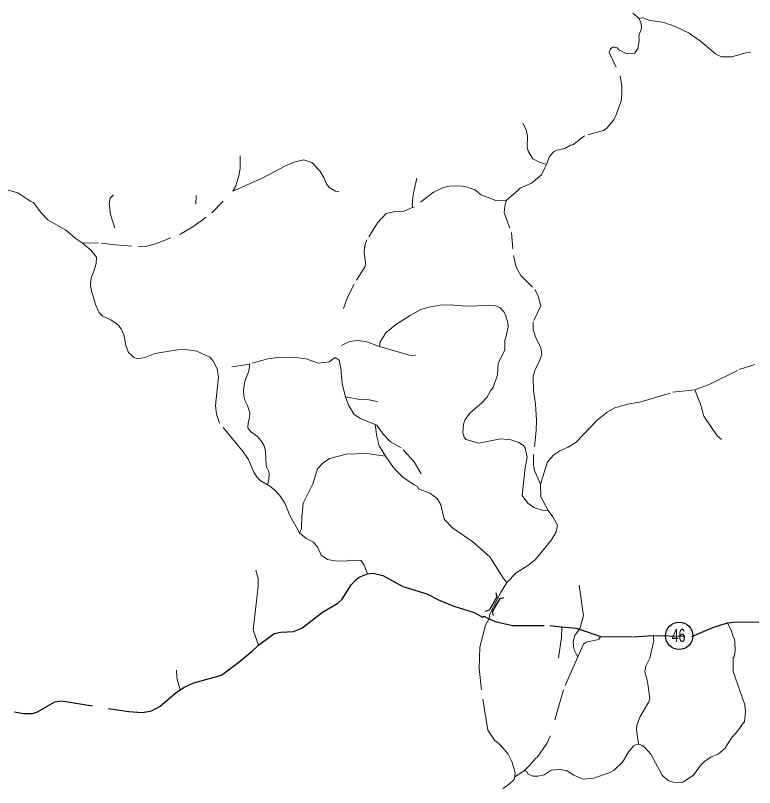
# Model space of a CAD drawing. Extents: x 423 to 448.8, y 7456.3 to 7484.
# Drawn here: x 428.721 to 433.228, y 7474.65 to 7479.36 of the extents above; entities that cross this region are included whole.
import ezdxf
from ezdxf.enums import TextEntityAlignment as Align

# ---------------------------------------------------------------- set-up
doc = ezdxf.new("R2010")
doc.units = 0
doc.header["$LTSCALE"] = 0.032
doc.linetypes.add('LONG_DASHED', pattern=[7.5, 6, -1.5])
doc.linetypes.add('MEDIUM_DASHED', pattern=[4.5, 3, -1.5])
for name, color, linetype, lineweight in [('10', 7, 'Continuous', 25), ('13', 7, 'Continuous', 25), ('4', 7, 'LONG_DASHED', 25), ('5', 7, 'LONG_DASHED', 13), ('6', 7, 'MEDIUM_DASHED', 13), ('7', 7, 'Continuous', 13)]:
    doc.layers.add(name, color=color, linetype=linetype, lineweight=lineweight)
doc.layers.add('61', color=7, linetype='Continuous')

msp = doc.modelspace()

# ---------------------------------------------------------------- linework, layer by layer
at = {"layer": '10'}
for p, q in [((431.6503, 7475.8371), (431.6569, 7475.8132)), ((431.6569, 7475.8132), (431.611, 7475.7329)), ((431.6742, 7475.8033), (431.6983, 7475.8097)), ((431.5869, 7475.7263), (431.611, 7475.7329))]:
    msp.add_line(p, q, dxfattribs=at)
msp.add_lwpolyline([(431.6742, 7475.8033), (431.6283, 7475.723), (431.6349, 7475.6988)], dxfattribs=at)
at = {"layer": '13'}
msp.add_circle((432.7679, 7475.5751), 0.083, dxfattribs=at)
at = {"layer": '4'}
msp.add_lwpolyline([(428.7159, 7475.1118), (428.7709, 7475.1024), (428.8258, 7475.1024), (428.8559, 7475.1107), (428.9615, 7475.1728), (429.0011, 7475.1779), (429.4133, 7475.1127), (429.4957, 7475.1066), (429.5507, 7475.1186), (429.6039, 7475.147), (429.6984, 7475.2278), (429.7254, 7475.2455), (429.7534, 7475.2638), (429.8084, 7475.2879), (429.9773, 7475.3363), (430.0754, 7475.4081), (430.163, 7475.4802), (430.2026, 7475.5183), (430.2987, 7475.5885), (430.3391, 7475.5971), (430.4164, 7475.6022), (430.468, 7475.6211), (430.5942, 7475.7198), (430.6878, 7475.7739), (430.7127, 7475.798), (430.7685, 7475.8856), (430.7977, 7475.9191), (430.8175, 7475.9328), (430.8685, 7475.9538), (430.9025, 7475.9578), (430.9609, 7475.9431), (431.0829, 7475.8753), (431.2289, 7475.8324), (431.301, 7475.7946), (431.3938, 7475.7568), (431.5174, 7475.7173), (431.5681, 7475.6898), (431.5765, 7475.6945), (431.6086, 7475.6794), (431.6463, 7475.6618), (431.7528, 7475.6391), (431.9804, 7475.6386), (432.0534, 7475.6307), (432.1407, 7475.6212), (432.159, 7475.6151), (432.2908, 7475.5712), (432.4891, 7475.5689), (432.6103, 7475.5769), (432.846, 7475.5713), (432.9741, 7475.6264), (433.0625, 7475.6536), (433.1166, 7475.6611), (433.254, 7475.6589)], dxfattribs=at)
at = {"layer": '5'}
for points in [[(430.8685, 7475.9538), (430.8483, 7476.0057), (430.8295, 7476.0345), (430.7618, 7476.036), (430.7359, 7476.0308), (430.6689, 7476.0333), (430.6243, 7476.0419), (430.5847, 7476.0677), (430.5641, 7476.1141), (430.5375, 7476.1458), (430.4937, 7476.169), (430.4533, 7476.2042), (430.3949, 7476.3099), (430.364, 7476.3838), (430.3314, 7476.4336), (430.303, 7476.4636), (430.2696, 7476.4894), (430.2574, 7476.4967), (430.2137, 7476.5229), (430.1931, 7476.5444), (430.1751, 7476.5727), (430.1416, 7476.65), (430.1089, 7476.6981), (429.9643, 7476.8735), (429.9475, 7476.9283), (429.9414, 7476.9798), (429.9595, 7477.155), (429.9518, 7477.2031), (429.9243, 7477.2546), (429.9054, 7477.2744), (429.8272, 7477.3113), (429.7585, 7477.3216), (429.7087, 7477.3199), (429.6332, 7477.3079), (429.572, 7477.2974), (429.5098, 7477.274), (429.4656, 7477.2646), (429.4428, 7477.2737), (429.4297, 7477.2868), (429.4111, 7477.3037), (429.3936, 7477.3473), (429.3815, 7477.4118), (429.3652, 7477.4479), (429.3514, 7477.4667), (429.3343, 7477.4796), (429.3025, 7477.502), (429.2544, 7477.526), (429.2312, 7477.5483), (429.2095, 7477.5964), (429.196, 7477.648), (429.1846, 7477.6774), (429.1783, 7477.7167), (429.1838, 7477.7593), (429.1969, 7477.7939), (429.2123, 7477.8472), (429.2149, 7477.8842), (429.1814, 7477.9271), (429.1273, 7477.9735), (429.0904, 7477.9975), (429.0275, 7478.0491), (428.9194, 7478.1126), (428.8782, 7478.1555), (428.831, 7478.2182), (428.8147, 7478.2242), (428.7348, 7478.2766), (428.6627, 7478.2973)], [(431.7668, 7474.7153), (431.7673, 7474.7425), (431.7476, 7474.8095), (431.7261, 7474.8541), (431.6772, 7474.9108), (431.6414, 7474.9393), (431.6021, 7474.9996), (431.5621, 7475.2449), (431.5492, 7475.3755), (431.5526, 7475.506), (431.5871, 7475.6407), (431.6081, 7475.6768), (431.6086, 7475.6794), (431.6145, 7475.7087), (431.6351, 7475.7534), (431.678, 7475.8366), (431.7177, 7475.901), (431.7734, 7475.9589), (431.8444, 7476.0038), (431.8893, 7476.0385), (431.9896, 7476.1602), (432.0175, 7476.21), (432.0253, 7476.2509), (431.9975, 7476.3021), (431.9683, 7476.3408), (431.9239, 7476.4222), (431.923, 7476.4996), (431.9655, 7476.6372), (432.0044, 7476.6792), (432.0414, 7476.7041), (432.0912, 7476.7264), (432.1375, 7476.7556), (432.2681, 7476.8905), (432.3282, 7476.9403), (432.3763, 7476.9669), (432.4536, 7476.9875), (432.5292, 7477.0012), (432.7301, 7477.0613), (432.8626, 7477.0765), (432.9517, 7477.1086), (433.1338, 7477.1996), (433.23, 7477.2314)], [(432.1512, 7475.4473), (432.1406, 7475.4656), (432.1304, 7475.4861), (432.1234, 7475.5102), (432.1214, 7475.54), (432.1328, 7475.5784), (432.1452, 7475.5953), (432.159, 7475.6151), (432.1591, 7475.6152), (432.1616, 7475.62), (432.1845, 7475.6967), (432.1588, 7475.8838)], [(432.0534, 7475.6307), (432.05, 7475.566), (432.0333, 7475.4419), (432.0338, 7475.4416)], [(432.2908, 7475.5712), (432.2851, 7475.5642), (432.2791, 7475.5557), (432.2675, 7475.5501), (432.2101, 7475.5388), (432.2011, 7475.536), (432.1945, 7475.532), (432.188, 7475.5279), (432.185, 7475.5241), (432.1512, 7475.4473)], [(432.1512, 7475.4473), (432.0628, 7475.2467), (431.9812, 7474.9632), (431.9606, 7474.9186), (431.903, 7474.8327), (431.8933, 7474.8288), (431.8544, 7474.7813), (431.8235, 7474.752), (431.7668, 7474.7153)], [(431.7668, 7474.7153), (431.7618, 7474.7015), (431.755, 7474.6931), (431.7368, 7474.6761), (431.7147, 7474.6587), (431.6937, 7474.644)]]:
    msp.add_lwpolyline(points, dxfattribs=at)
at = {"layer": '6'}
for points in [[(432.4864, 7479.3735), (432.5248, 7479.3407), (432.5365, 7479.3095), (432.538, 7479.2821), (432.5223, 7479.2351), (432.524, 7479.2067), (432.5163, 7479.1561), (432.4965, 7479.1295), (432.4493, 7479.1252), (432.401, 7479.1509), (432.3892, 7479.1621), (432.3746, 7479.1656), (432.3634, 7479.1664), (432.3497, 7479.1561), (432.341, 7479.1346), (432.4089, 7478.992), (432.4192, 7478.9277), (432.4192, 7478.8727), (432.4141, 7478.8374), (432.3848, 7478.7525), (432.3703, 7478.7233), (432.3265, 7478.6717), (432.3076, 7478.6579), (432.1899, 7478.6253), (432.1195, 7478.5712), (432.1057, 7478.5687), (432.0705, 7478.5489), (432.0225, 7478.5369), (432.0027, 7478.5276), (431.9779, 7478.5), (431.968, 7478.4718), (431.9587, 7478.4505), (431.9496, 7478.4297), (431.9287, 7478.3878), (431.8685, 7478.3375), (431.7994, 7478.3057), (431.7844, 7478.2924), (431.7147, 7478.2326)], [(429.1273, 7477.9735), (429.2431, 7477.9704), (429.3315, 7477.9594), (429.4717, 7477.9502), (429.5206, 7477.952), (429.5748, 7477.9657), (429.7228, 7478.0244), (429.8034, 7478.0703), (429.9194, 7478.155), (430.0473, 7478.2885), (430.0627, 7478.3144), (430.0822, 7478.3815), (430.0919, 7478.4269), (430.0917, 7478.504)], [(431.7147, 7478.2326), (431.651, 7478.2306), (431.5604, 7478.2646), (431.5226, 7478.2964), (431.478, 7478.3119), (431.447, 7478.3187), (431.3757, 7478.3196), (431.3319, 7478.311), (431.2701, 7478.2809), (431.1518, 7478.1909), (431.1422, 7478.1872), (431.1315, 7478.1831), (431.0871, 7478.164), (431.0443, 7478.165), (430.9824, 7478.1513), (430.9282, 7478.0946), (430.8644, 7477.9908), (430.8505, 7477.9559), (430.8544, 7477.9502), (430.8492, 7477.9434), (430.8467, 7477.9159), (430.8553, 7477.849), (430.8536, 7477.8292), (430.7857, 7477.7201), (430.7462, 7477.6419), (430.7214, 7477.5727)], [(431.7147, 7478.2326), (431.7042, 7478.1972), (431.7003, 7478.1564), (431.7465, 7478.0362), (431.7579, 7477.8953), (431.7751, 7477.8232), (431.8034, 7477.7734), (431.8876, 7477.6874), (431.9065, 7477.6531), (431.9246, 7477.5887), (431.8781, 7477.49), (431.8782, 7477.4461), (431.8928, 7477.3972), (431.9254, 7477.3336), (431.9314, 7477.2924), (431.9134, 7477.2426), (431.8876, 7477.1962), (431.8782, 7477.1524), (431.8807, 7477.0726), (431.8919, 7476.9875), (431.8979, 7476.8888), (431.8971, 7476.8277), (431.8807, 7476.6809), (431.8798, 7476.6157), (431.8867, 7476.583), (431.923, 7476.4996)], [(431.1948, 7476.5637), (431.1514, 7476.636), (431.073, 7476.7229), (431.0086, 7476.7594), (430.961, 7476.8071), (430.9245, 7476.8609), (430.9137, 7476.8653), (430.8252, 7476.9011), (430.786, 7476.9264), (430.7517, 7476.9825), (430.7345, 7477.034), (430.7127, 7477.1118), (430.704, 7477.2136), (430.6945, 7477.2573), (430.6712, 7477.2733), (430.6334, 7477.2476), (430.569, 7477.2392), (430.4934, 7477.2644), (430.4267, 7477.2735), (430.334, 7477.2752), (430.2609, 7477.2649), (430.1502, 7477.2344), (430.139, 7477.2314), (429.9518, 7477.2031)]]:
    msp.add_lwpolyline(points, dxfattribs=at)
at = {"layer": '7'}
msp.add_line((429.8238, 7478.2608), (429.8206, 7478.2089), dxfattribs=at)
for points in [[(433.2057, 7479.1354), (433.1655, 7479.1297), (433.0894, 7479.1067), (433.0263, 7479.1082), (432.9904, 7479.1254), (432.8976, 7479.2033), (432.8254, 7479.2531), (432.7439, 7479.2918), (432.6691, 7479.3193), (432.5901, 7479.3296), (432.5464, 7479.3459), (432.5248, 7479.3407)], [(431.8141, 7478.7031), (431.8352, 7478.6636), (431.8441, 7478.6228), (431.841, 7478.5582), (431.8469, 7478.5318), (431.8755, 7478.4844), (431.8888, 7478.4798), (431.9173, 7478.4647), (431.9587, 7478.4505)], [(430.0473, 7478.2885), (430.2222, 7478.3652), (430.3683, 7478.4415), (430.4262, 7478.4659), (430.4804, 7478.4795), (430.5282, 7478.4626), (430.577, 7478.4128), (430.6039, 7478.3679), (430.6163, 7478.336), (430.6343, 7478.3101), (430.6731, 7478.2872), (430.693, 7478.2862)], [(431.1695, 7478.3678), (431.1505, 7478.2866), (431.1437, 7478.2493), (431.1391, 7478.2016), (431.1422, 7478.1872)], [(429.3198, 7478.2654), (429.2981, 7478.2455), (429.2916, 7478.2148), (429.3005, 7478.1461), (429.3272, 7478.063)], [(431.9683, 7476.3408), (431.9333, 7476.3425), (431.8812, 7476.3574), (431.8449, 7476.3849), (431.8115, 7476.4315), (431.8291, 7476.6001), (431.8403, 7476.6653), (431.8282, 7476.7203), (431.8182, 7476.7373), (431.7903, 7476.7551), (431.7408, 7476.7706), (431.6794, 7476.7762), (431.5468, 7476.7504), (431.4677, 7476.7736), (431.4569, 7476.7873), (431.448, 7476.8141), (431.4522, 7476.867), (431.4623, 7476.8956), (431.4909, 7476.9331), (431.5641, 7476.9962), (431.595, 7477.029), (431.6181, 7477.0707), (431.6349, 7477.0903), (431.6599, 7477.1667), (431.6637, 7477.2375), (431.7055, 7477.3207), (431.7055, 7477.3783), (431.7141, 7477.4024), (431.7244, 7477.4625), (431.7236, 7477.4839), (431.709, 7477.5329), (431.6986, 7477.5518), (431.6755, 7477.5775), (431.648, 7477.5887), (431.6119, 7477.5913), (431.4659, 7477.587), (431.3732, 7477.5939), (431.3113, 7477.593), (431.2409, 7477.581), (431.1936, 7477.5655), (431.1275, 7477.5303), (431.0382, 7477.4719), (430.9824, 7477.4247), (430.9446, 7477.368), (430.9405, 7477.3403)], [(430.9405, 7477.3403), (430.857, 7477.3705), (430.8046, 7477.3774), (430.7582, 7477.3706), (430.709, 7477.3465)], [(430.9405, 7477.3403), (431.1296, 7477.2845), (431.16, 7477.288)], [(430.1502, 7477.2344), (430.1436, 7477.1897), (430.1194, 7477.1293), (430.1122, 7477.0764), (430.1134, 7477.038), (430.1198, 7477.0127), (430.137, 7476.9807), (430.1503, 7476.9362), (430.1474, 7476.905), (430.1392, 7476.8756), (430.1383, 7476.845), (430.1543, 7476.8208), (430.1979, 7476.7917), (430.2194, 7476.7651), (430.2385, 7476.7343), (430.2462, 7476.6998), (430.2492, 7476.6191), (430.2518, 7476.607), (430.2631, 7476.5828), (430.2685, 7476.5656), (430.2669, 7476.526), (430.2574, 7476.4967)], [(432.8626, 7477.0765), (432.898, 7476.9879), (432.9175, 7476.9153), (432.9989, 7476.7951), (433.0264, 7476.7736)], [(430.9281, 7477.0029), (430.917, 7477.0068), (430.8879, 7477.0129), (430.8523, 7477.0182), (430.8218, 7477.0178), (430.7345, 7477.034)], [(430.9137, 7476.8653), (430.9239, 7476.7906), (430.9389, 7476.7338), (430.9766, 7476.6722)], [(430.4533, 7476.2042), (430.466, 7476.228), (430.4682, 7476.3058), (430.4686, 7476.3156), (430.4758, 7476.3854), (430.5346, 7476.5023), (430.5624, 7476.5934), (430.5962, 7476.6283), (430.6367, 7476.6569), (430.7382, 7476.6837), (430.8642, 7476.6871), (430.9766, 7476.6722)], [(430.9766, 7476.6722), (431.0322, 7476.5941), (431.0828, 7476.5426), (431.1516, 7476.4954), (431.1722, 7476.4859), (431.1791, 7476.4713), (431.2486, 7476.4456), (431.2915, 7476.4138), (431.3156, 7476.3743), (431.3362, 7476.2867), (431.3852, 7476.2343), (431.5097, 7476.1493), (431.6127, 7476.0574), (431.6973, 7475.9244), (431.7177, 7475.901)], [(430.2026, 7475.5183), (430.1707, 7475.6119), (430.2017, 7475.877), (430.2017, 7475.926), (430.1871, 7475.9758)], [(433.0625, 7475.6536), (433.0865, 7475.6033), (433.1002, 7475.5621), (433.1037, 7475.5618), (433.1072, 7475.5404), (433.1089, 7475.4854), (433.1037, 7475.4467), (433.0968, 7475.4408), (433.0981, 7475.3575), (433.1543, 7475.1941), (433.169, 7475.1544), (433.1735, 7475.1112), (433.1667, 7475.0523), (433.1245, 7474.994), (433.0908, 7474.9563), (433.0623, 7474.9147), (433.048, 7474.8893), (433.0065, 7474.8532), (432.9635, 7474.8381), (432.9225, 7474.8095), (432.8976, 7474.7837), (432.8564, 7474.7253), (432.7911, 7474.6824), (432.7387, 7474.6798), (432.7054, 7474.6914), (432.676, 7474.7124), (432.664, 7474.7244), (432.5962, 7474.8541), (432.5589, 7474.8946), (432.54, 7474.9078), (432.5192, 7474.9138)], [(432.6103, 7475.5769), (432.6131, 7475.5451), (432.5882, 7475.4392), (432.5749, 7475.4109), (432.5642, 7475.3902), (432.5599, 7475.3679), (432.559, 7475.3566), (432.5621, 7475.3417), (432.5681, 7475.3196), (432.5736, 7475.3055), (432.5781, 7475.2675), (432.5884, 7475.1908), (432.5824, 7475.1728), (432.5277, 7475.0801), (432.5095, 7475.0277), (432.5079, 7475.0018), (432.5192, 7474.9138)], [(429.7029, 7475.365), (429.7043, 7475.3198), (429.7254, 7475.2455)], [(432.5192, 7474.9138), (432.502, 7474.91), (432.4898, 7474.9041), (432.4768, 7474.8878), (432.4609, 7474.8692), (432.4223, 7474.8048), (432.3721, 7474.7558), (432.3452, 7474.7418), (432.2482, 7474.7075), (432.1813, 7474.7004), (432.1255, 7474.7253), (432.0817, 7474.7528), (432.0405, 7474.7606), (431.9872, 7474.7554), (431.9444, 7474.7265), (431.9066, 7474.7185), (431.8748, 7474.7185), (431.8464, 7474.732), (431.8365, 7474.749), (431.8235, 7474.752)]]:
    msp.add_lwpolyline(points, dxfattribs=at)

# ---------------------------------------------------------------- texts
at = {"layer": '61', "width": 0.7}
msp.add_text('46', height=0.08, dxfattribs=at).set_placement((432.7645, 7475.5379), align=Align.CENTER)

doc.saveas('drawing.dxf')
